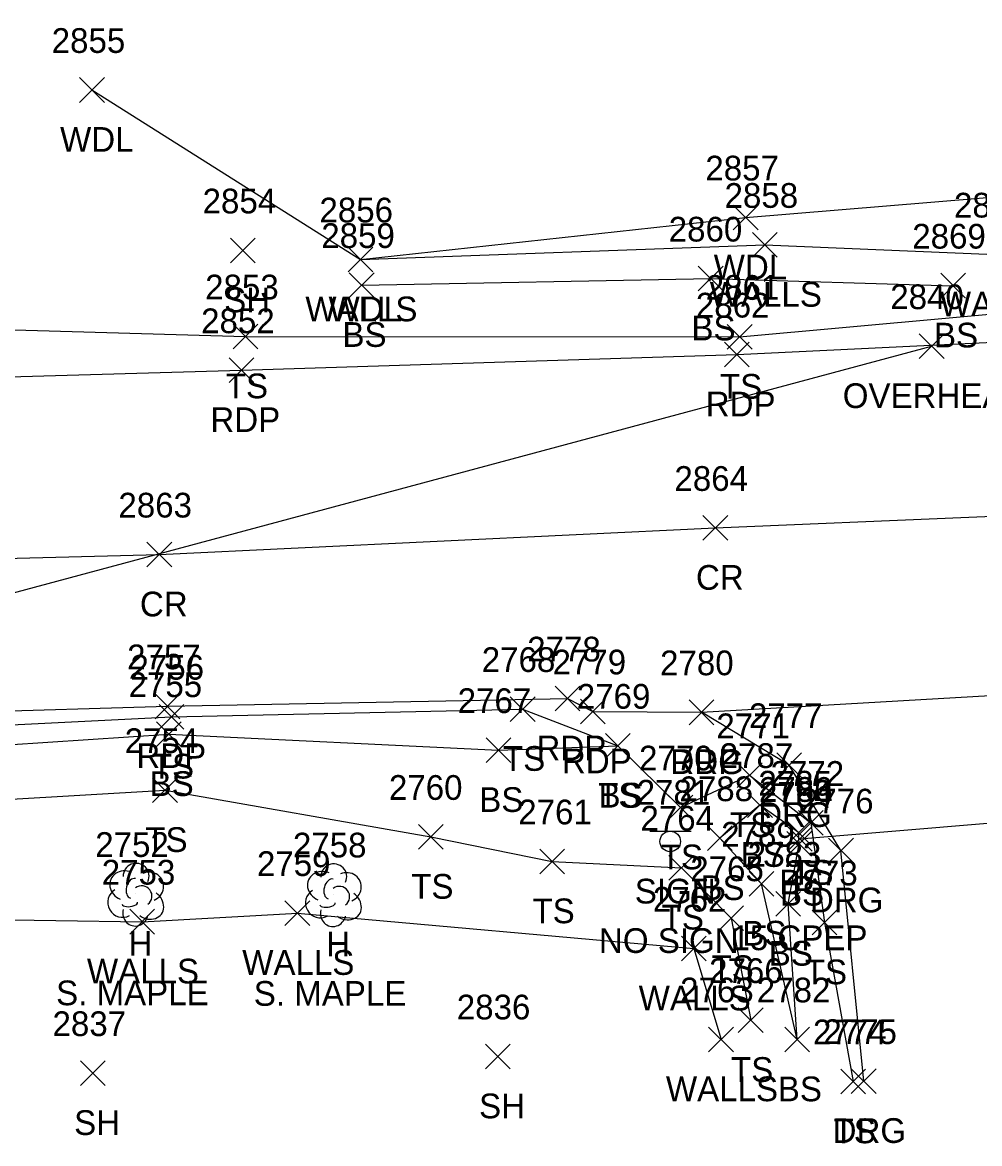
# Model space of a CAD drawing. Extents: x 1611797 to 1633212, y 298978 to 305475.
# Drawn here: x 1616071.8 to 1616149.2, y 301459.3 to 301550 of the extents above; entities that cross this region are included whole.
import ezdxf

# ---------------------------------------------------------------- set-up
doc = ezdxf.new("R2010")
doc.units = 0
for name, color, linetype in [('D_A', 7, 'Continuous'), ('D_C', 7, 'Continuous'), ('D_I', 7, 'Continuous'), ('D_TIC', 7, 'Continuous'), ('DCP', 7, 'Continuous'), ('L_A', 7, 'Continuous'), ('L_C', 7, 'Continuous'), ('L_I', 7, 'Continuous'), ('L_TIC', 7, 'Continuous'), ('LAWA', 7, 'Continuous'), ('LELB', 7, 'Continuous'), ('LTD', 7, 'Continuous'), ('LWS', 7, 'Continuous'), ('P_A', 7, 'Continuous'), ('P_I', 7, 'Continuous'), ('P_TIC', 7, 'Continuous'), ('PET', 7, 'Continuous'), ('PRC', 7, 'Continuous'), ('R_A', 7, 'Continuous'), ('R_I', 7, 'Continuous'), ('R_TIC', 7, 'Continuous'), ('RDG', 7, 'Continuous'), ('S_A', 7, 'Continuous'), ('S_C', 7, 'Continuous'), ('S_I', 7, 'Continuous'), ('SSGN', 7, 'Continuous'), ('U_A', 7, 'Continuous'), ('U_I', 7, 'Continuous'), ('U_TIC', 7, 'Continuous'), ('UCO', 7, 'Continuous')]:
    doc.layers.add(name, color=color, linetype=linetype)

msp = doc.modelspace()

# ---------------------------------------------------------------- linework, layer by layer
at = {"layer": 'D_TIC'}
for points in [[(1616133.638, 301482.967), (1616135.638, 301484.967)], [(1616135.638, 301482.967), (1616133.638, 301484.967)]]:
    msp.add_lwpolyline(points, dxfattribs=at)
at = {"layer": 'DCP'}
msp.add_lwpolyline([(1616134.638, 301483.967), (1616157.571, 301485.883)], dxfattribs=at)
at = {"layer": 'L_TIC'}
for points in [[(1616076.397, 301543.561), (1616078.397, 301545.561)], [(1616078.397, 301543.561), (1616076.397, 301545.561)], [(1616129.251, 301533.239), (1616131.251, 301535.239)], [(1616131.251, 301533.239), (1616129.251, 301535.239)], [(1616088.6, 301530.574), (1616090.6, 301532.574)], [(1616090.6, 301530.574), (1616088.6, 301532.574)], [(1616130.806, 301531.026), (1616132.806, 301533.026)], [(1616132.806, 301531.026), (1616130.806, 301533.026)], [(1616098.104, 301529.847), (1616100.104, 301531.847)], [(1616100.104, 301529.847), (1616098.104, 301531.847)], [(1616098.104, 301529.847), (1616100.104, 301531.847)], [(1616100.104, 301529.847), (1616098.104, 301531.847)], [(1616098.204, 301527.777), (1616100.204, 301529.777)], [(1616100.204, 301527.777), (1616098.204, 301529.777)], [(1616126.425, 301528.3), (1616128.425, 301530.3)], [(1616128.425, 301528.3), (1616126.425, 301530.3)], [(1616146.038, 301527.729), (1616148.038, 301529.729)], [(1616148.038, 301527.729), (1616146.038, 301529.729)], [(1616088.806, 301523.619), (1616090.806, 301525.619)], [(1616090.806, 301523.619), (1616088.806, 301525.619)], [(1616128.765, 301523.584), (1616130.765, 301525.584)], [(1616130.765, 301523.584), (1616128.765, 301525.584)], [(1616111.219, 301493.476), (1616113.219, 301495.476)], [(1616113.219, 301493.476), (1616111.219, 301495.476)], [(1616082.823, 301492.853), (1616084.823, 301494.853)], [(1616084.823, 301492.853), (1616082.823, 301494.853)], [(1616082.615, 301491.441), (1616084.615, 301493.441)], [(1616084.615, 301491.441), (1616082.615, 301493.441)], [(1616118.914, 301490.503), (1616120.914, 301492.503)], [(1616120.914, 301490.503), (1616118.914, 301492.503)], [(1616118.914, 301490.503), (1616120.914, 301492.503)], [(1616120.914, 301490.503), (1616118.914, 301492.503)], [(1616109.268, 301490.152), (1616111.268, 301492.152)], [(1616111.268, 301490.152), (1616109.268, 301492.152)], [(1616129.575, 301488.116), (1616131.575, 301490.116)], [(1616131.575, 301488.116), (1616129.575, 301490.116)], [(1616082.301, 301486.913), (1616084.301, 301488.913)], [(1616084.301, 301486.913), (1616082.301, 301488.913)], [(1616123.978, 301485.509), (1616125.978, 301487.509)], [(1616125.978, 301485.509), (1616123.978, 301487.509)], [(1616130.41, 301485.707), (1616132.41, 301487.707)], [(1616132.41, 301485.707), (1616130.41, 301487.707)], [(1616134.527, 301484.261), (1616136.527, 301486.261)], [(1616136.527, 301484.261), (1616134.527, 301486.261)], [(1616103.801, 301483.129), (1616105.801, 301485.129)], [(1616105.801, 301483.129), (1616103.801, 301485.129)], [(1616133.536, 301483.475), (1616135.536, 301485.475)], [(1616135.536, 301483.475), (1616133.536, 301485.475)], [(1616127.16, 301483.022), (1616129.16, 301485.022)], [(1616129.16, 301483.022), (1616127.16, 301485.022)], [(1616133.585, 301482.571), (1616135.585, 301484.571)], [(1616135.585, 301482.571), (1616133.585, 301484.571)], [(1616113.603, 301481.147), (1616115.603, 301483.147)], [(1616115.603, 301481.147), (1616113.603, 301483.147)], [(1616124.051, 301480.638), (1616126.051, 301482.638)], [(1616126.051, 301480.638), (1616124.051, 301482.638)], [(1616130.541, 301479.34), (1616132.541, 301481.34)], [(1616132.541, 301479.34), (1616130.541, 301481.34)], [(1616130.541, 301479.34), (1616132.541, 301481.34)], [(1616132.541, 301479.34), (1616130.541, 301481.34)], [(1616132.68, 301477.715), (1616134.68, 301479.715)], [(1616134.68, 301477.715), (1616132.68, 301479.715)], [(1616093.001, 301476.969), (1616095.001, 301478.969)], [(1616095.001, 301476.969), (1616093.001, 301478.969)], [(1616080.444, 301476.273), (1616082.444, 301478.273)], [(1616082.444, 301476.273), (1616080.444, 301478.273)], [(1616128.08, 301476.548), (1616130.08, 301478.548)], [(1616130.08, 301476.548), (1616128.08, 301478.548)], [(1616135.623, 301476.209), (1616137.623, 301478.209)], [(1616137.623, 301476.209), (1616135.623, 301478.209)], [(1616125.056, 301474.091), (1616127.056, 301476.091)], [(1616127.056, 301474.091), (1616125.056, 301476.091)], [(1616129.659, 301468.311), (1616131.659, 301470.311)], [(1616131.659, 301468.311), (1616129.659, 301470.311)], [(1616127.26, 301466.747), (1616129.26, 301468.747)], [(1616129.26, 301466.747), (1616127.26, 301468.747)], [(1616133.411, 301466.743), (1616135.411, 301468.743)], [(1616135.411, 301466.743), (1616133.411, 301468.743)], [(1616133.411, 301466.743), (1616135.411, 301468.743)], [(1616135.411, 301466.743), (1616133.411, 301468.743)], [(1616109.209, 301465.366), (1616111.209, 301467.366)], [(1616111.209, 301465.366), (1616109.209, 301467.366)], [(1616076.465, 301464.017), (1616078.465, 301466.017)], [(1616078.465, 301464.017), (1616076.465, 301466.017)], [(1616137.952, 301463.348), (1616139.952, 301465.348)], [(1616139.952, 301463.348), (1616137.952, 301465.348)]]:
    msp.add_lwpolyline(points, dxfattribs=at)
at = {"layer": 'LAWA'}
msp.add_lwpolyline([(1616077.397, 301544.561), (1616099.104, 301530.847), (1616130.251, 301534.239), (1616168.347, 301537.406), (1616206, 301540.224), (1616235.198, 301540.836), (1616280.164, 301546.271), (1616301.611, 301541.255), (1616300.857, 301550.027)], dxfattribs=at)
at = {"layer": 'LELB'}
for points in [[(1615704.044, 301519.429), (1615721.872, 301519.336), (1615766.347, 301519.497), (1615808.064, 301519.863), (1615851.206, 301519.772), (1615891.691, 301519.156), (1615938.875, 301519.331), (1615967.204, 301520.797), (1616008.295, 301523.113), (1616049.597, 301525.777), (1616089.806, 301524.619), (1616129.765, 301524.584), (1616155.631, 301526.935), (1616173.613, 301534.481), (1616188.642, 301527.741), (1616206.16, 301529.587), (1616236.465, 301530.233), (1616280.018, 301532.647)], [(1616099.204, 301528.777), (1616127.425, 301529.3), (1616147.038, 301528.729)], [(1615989.779, 301484.607), (1615994.61, 301488.827), (1616015.481, 301490.69), (1616050.954, 301492.21), (1616083.823, 301493.853), (1616112.219, 301494.476), (1616119.914, 301491.503), (1616124.978, 301486.509), (1616130.575, 301489.116), (1616135.527, 301485.261), (1616136.623, 301477.209), (1616138.952, 301464.348)], [(1615989.574, 301477.425), (1615992.854, 301483.301), (1616014.972, 301485.96), (1616050.97, 301490.273), (1616083.615, 301492.441), (1616110.268, 301491.152), (1616119.914, 301491.503)], [(1616042.737, 301484.507), (1616050.632, 301486.008), (1616083.301, 301487.913), (1616104.801, 301484.129), (1616114.603, 301482.147), (1616125.051, 301481.638), (1616129.08, 301477.548), (1616130.659, 301469.311)], [(1616134.411, 301467.743), (1616133.68, 301478.715), (1616134.585, 301483.571), (1616134.536, 301484.475), (1616131.41, 301486.707), (1616128.16, 301484.022), (1616131.541, 301480.34)], [(1616134.411, 301467.743), (1616131.541, 301480.34)]]:
    msp.add_lwpolyline(points, dxfattribs=at)
at = {"layer": 'LTD'}
for p, q in [((1616080.92, 301479.512), (1616080.92, 301479.512)), ((1616080.92, 301479.512), (1616080.92, 301479.512)), ((1616096.904, 301479.468), (1616096.904, 301479.468)), ((1616096.904, 301479.468), (1616096.904, 301479.468))]:
    msp.add_line(p, q, dxfattribs=at)
for centre in [(1616080.967, 301480.946), (1616096.951, 301480.902)]:
    msp.add_arc(centre, 1.047, 335.52715, 180.95627, dxfattribs=at)
for centre, major_axis, ratio, start_param, end_param in [((1616080.128, 301480.179), (1.21, -0.512), 0.895232, 1.570796, 4.712389), ((1616096.113, 301480.134), (1.21, -0.512), 0.895232, 1.570796, 4.712389), ((1616080.711, 301479.97), (-0.208, -0.792), 0.645439, 3.141593, 6.283185), ((1616081.961, 301480.096), (-1.141, -0.483), 0.949671, 1.570796, 4.712389), ((1616096.696, 301479.926), (-0.208, -0.792), 0.645439, 3.141593, 6.283185), ((1616097.946, 301480.051), (-1.141, -0.483), 0.949671, 1.570796, 4.712389), ((1616079.837, 301478.804), (0.584, -1.042), 0.959034, 3.141593, 6.283185), ((1616081.42, 301479.346), (-0.5, 0.667), 0.989748, 3.141593, 6.283185), ((1616095.821, 301478.759), (0.584, -1.042), 0.959034, 3.141593, 6.283185), ((1616097.404, 301479.301), (-0.5, 0.667), 0.989748, 3.141593, 6.283185), ((1616080.462, 301478.762), (-0.625, -0.083), 0.423636, 0, 3.141593), ((1616081.92, 301478.679), (-1.09, 0.792), 0.841452, 1.570796, 4.712389), ((1616096.446, 301478.718), (-0.625, -0.083), 0.423636, 0, 3.141593), ((1616097.905, 301478.634), (-1.09, 0.792), 0.841452, 1.570796, 4.712389), ((1616080.92, 301478.012), (0.265, 1.061), 0.942809, 1.570796, 4.712389), ((1616096.905, 301477.968), (0.265, 1.061), 0.942809, 1.570796, 4.712389)]:
    msp.add_ellipse(centre, major_axis=major_axis, ratio=ratio, start_param=start_param, end_param=end_param, dxfattribs=at)
at = {"layer": 'LWS'}
for points in [[(1616099.104, 301530.847), (1616131.806, 301532.026), (1616150.407, 301531.242)], [(1615991.045, 301479.401), (1616009.193, 301477.842), (1616046.524, 301477.786), (1616081.444, 301477.273), (1616094.001, 301477.969), (1616126.056, 301475.091), (1616128.26, 301467.747)]]:
    msp.add_lwpolyline(points, dxfattribs=at)
at = {"layer": 'P_TIC'}
for points in [[(1616128.535, 301522.151), (1616130.535, 301524.151)], [(1616130.535, 301522.151), (1616128.535, 301524.151)], [(1616088.483, 301520.885), (1616090.483, 301522.885)], [(1616090.483, 301520.885), (1616088.483, 301522.885)], [(1616126.799, 301508.126), (1616128.799, 301510.126)], [(1616128.799, 301508.126), (1616126.799, 301510.126)], [(1616081.84, 301505.971), (1616083.84, 301507.971)], [(1616083.84, 301505.971), (1616081.84, 301507.971)], [(1616114.848, 301494.324), (1616116.848, 301496.324)], [(1616116.848, 301494.324), (1616114.848, 301496.324)], [(1616082.497, 301493.695), (1616084.497, 301495.695)], [(1616084.497, 301493.695), (1616082.497, 301495.695)], [(1616116.905, 301493.278), (1616118.905, 301495.278)], [(1616118.905, 301493.278), (1616116.905, 301495.278)], [(1616125.676, 301493.21), (1616127.676, 301495.21)], [(1616127.676, 301493.21), (1616125.676, 301495.21)]]:
    msp.add_lwpolyline(points, dxfattribs=at)
at = {"layer": 'PET'}
for points in [[(1615966.818, 301518.281), (1616008.879, 301518.723), (1616050.011, 301520.759), (1616089.483, 301521.885), (1616129.535, 301523.151), (1616168.159, 301525.02), (1616195.535, 301526.207), (1616237.725, 301528.278), (1616279.261, 301529.047), (1616310.093, 301528.737), (1616346.909, 301526.936), (1616396.487, 301523.415), (1616418.702, 301521.734), (1616433.776, 301520.787), (1616436.26, 301522.002), (1616473.653, 301518.392)], [(1615957.121, 301489.367), (1615991.141, 301489.805), (1615993.646, 301491.148), (1616015.443, 301492.405), (1616050.86, 301493.726), (1616083.497, 301494.695), (1616115.848, 301495.324), (1616117.905, 301494.278), (1616126.676, 301494.21), (1616158.881, 301496.09), (1616172.109, 301497.829), (1616239.299, 301501.678), (1616275.912, 301502.338), (1616312.403, 301501.843), (1616375.815, 301498.508), (1616390.517, 301497.388), (1616390.666, 301497.624), (1616429.451, 301494.362), (1616470.741, 301491.131)]]:
    msp.add_lwpolyline(points, dxfattribs=at)
at = {"layer": 'PRC'}
msp.add_lwpolyline([(1615915.553, 301503.017), (1616010.706, 301505.129), (1616082.84, 301506.971), (1616127.799, 301509.126), (1616168.819, 301510.867), (1616237.813, 301513.845), (1616278.388, 301514.303), (1616314.288, 301513.683), (1616391.362, 301509.478), (1616432.286, 301506.326), (1616472.786, 301503.519), (1616513.149, 301500.749), (1616529.077, 301499.503), (1616571.59, 301496.851)], dxfattribs=at)
at = {"layer": 'R_TIC'}
for points in [[(1616125.676, 301493.21), (1616127.676, 301495.21)], [(1616127.676, 301493.21), (1616125.676, 301495.21)], [(1616132.776, 301488.936), (1616134.776, 301490.936)], [(1616134.776, 301488.936), (1616132.776, 301490.936)], [(1616136.959, 301482.027), (1616138.959, 301484.027)], [(1616138.959, 301482.027), (1616136.959, 301484.027)], [(1616138.794, 301463.373), (1616140.794, 301465.373)], [(1616140.794, 301463.373), (1616138.794, 301465.373)]]:
    msp.add_lwpolyline(points, dxfattribs=at)
at = {"layer": 'RDG'}
msp.add_lwpolyline([(1616139.794, 301464.373), (1616137.959, 301483.027), (1616133.776, 301489.936), (1616126.676, 301494.21)], dxfattribs=at)
at = {"layer": 'SSGN'}
for p, q in [((1616122.503, 301484.596), (1616125.836, 301484.596)), ((1616124.15, 301483.763), (1616124.15, 301483.763))]:
    msp.add_line(p, q, dxfattribs=at)
msp.add_circle((1616124.15, 301483.763), 0.833, dxfattribs=at)
at = {"layer": 'U_TIC'}
for points in [[(1616144.29, 301522.829), (1616146.29, 301524.829)], [(1616146.29, 301522.829), (1616144.29, 301524.829)]]:
    msp.add_lwpolyline(points, dxfattribs=at)
at = {"layer": 'UCO'}
msp.add_lwpolyline([(1616031.599, 301493.267), (1616145.29, 301523.829)], dxfattribs=at)

# ---------------------------------------------------------------- texts
at = {"layer": 'D_A'}
msp.add_text('P', height=2, dxfattribs=at).set_placement((1616134.016, 301478.967))
at = {"layer": 'D_C'}
msp.add_text('15 CPEP', height=2, dxfattribs=at).set_placement((1616129.103, 301474.967))
at = {"layer": 'D_I'}
msp.add_text('2786', height=2, dxfattribs=at).set_placement((1616131.323, 301486.967))
at = {"layer": 'L_A'}
for s, p in [('WDL', (1616074.815, 301539.561)), ('WDL', (1616127.668, 301529.239)), ('WALLS', (1616127.35, 301527.026)), ('SH', (1616088.088, 301526.574)), ('WALLS', (1616094.647, 301525.847)), ('WDL', (1616096.521, 301525.847)), ('WALLS', (1616145.95, 301526.242)), ('BS', (1616125.866, 301524.3)), ('BS', (1616097.645, 301523.777)), ('BS', (1616145.479, 301523.729)), ('TS', (1616088.215, 301519.619)), ('TS', (1616128.174, 301519.584)), ('TS', (1616110.629, 301489.476)), ('TS', (1616082.233, 301488.853)), ('BS', (1616082.056, 301487.441)), ('BS', (1616108.709, 301486.152)), ('TS', (1616118.324, 301486.503)), ('BS', (1616118.355, 301486.503)), ('TS', (1616128.984, 301484.116)), ('TS', (1616081.71, 301482.913)), ('TS', (1616123.387, 301481.509)), ('BS', (1616129.851, 301481.707)), ('BS', (1616132.977, 301479.475)), ('TS', (1616133.937, 301480.261)), ('TS', (1616103.21, 301479.129)), ('BS', (1616126.601, 301479.022)), ('BS', (1616133.026, 301478.571)), ('TS', (1616113.013, 301477.147)), ('TS', (1616123.461, 301476.638)), ('BS', (1616129.982, 301475.34)), ('BS', (1616129.982, 301475.34)), ('H', (1616080.353, 301474.512)), ('H', (1616096.337, 301474.468)), ('BS', (1616132.121, 301473.715)), ('WALLS', (1616076.987, 301472.273)), ('WALLS', (1616089.545, 301472.969)), ('TS', (1616127.49, 301472.548)), ('TS', (1616135.033, 301472.209)), ('WALLS', (1616121.6, 301470.091)), ('TS', (1616129.068, 301464.311)), ('WALLS', (1616123.804, 301462.747)), ('BS', (1616132.852, 301462.743)), ('BS', (1616132.852, 301462.743)), ('SH', (1616108.697, 301461.366)), ('SH', (1616075.953, 301460.017)), ('TS', (1616137.362, 301459.348))]:
    msp.add_text(s, height=2, dxfattribs=at).set_placement(p)
at = {"layer": 'L_C'}
for p in [(1616074.495, 301470.512), (1616090.479, 301470.468)]:
    msp.add_text('S. MAPLE', height=2, dxfattribs=at).set_placement(p)
at = {"layer": 'L_I'}
for s, p in [('2855', (1616074.138, 301547.561)), ('2857', (1616126.991, 301537.239)), ('2858', (1616128.546, 301535.026)), ('2854', (1616086.34, 301534.574)), ('2868', (1616147.1, 301534.242)), ('2856', (1616095.789, 301533.847)), ('2856', (1616095.789, 301533.847)), ('2860', (1616124.031, 301532.3)), ('2859', (1616095.937, 301531.777)), ('2869', (1616143.723, 301531.729)), ('2853', (1616086.546, 301527.619)), ('2861', (1616127.025, 301527.584)), ('2756', (1616080.508, 301496.853)), ('2768', (1616108.912, 301497.476)), ('2755', (1616080.355, 301495.441)), ('2767', (1616106.961, 301494.152)), ('2769', (1616116.6, 301494.503)), ('2769', (1616116.6, 301494.503)), ('2771', (1616127.882, 301492.116)), ('2754', (1616080.041, 301490.913)), ('2770', (1616121.631, 301489.509)), ('2787', (1616128.15, 301489.707)), ('2772', (1616132.268, 301488.261)), ('2760', (1616101.407, 301487.129)), ('2788', (1616124.901, 301487.022)), ('2785', (1616131.276, 301487.475)), ('2784', (1616131.326, 301486.571)), ('2761', (1616111.863, 301485.147)), ('2764', (1616121.744, 301484.638)), ('2789', (1616128.273, 301483.34)), ('2789', (1616128.273, 301483.34)), ('2752', (1616077.66, 301482.512)), ('2758', (1616093.645, 301482.468)), ('2783', (1616130.421, 301481.715)), ('2759', (1616090.734, 301480.969)), ('2765', (1616125.773, 301480.548)), ('2753', (1616078.184, 301480.273)), ('2773', (1616133.364, 301480.209)), ('2762', (1616122.749, 301478.091)), ('2766', (1616127.297, 301472.311)), ('2763', (1616124.953, 301470.747)), ('2782', (1616131.152, 301470.743)), ('2782', (1616131.152, 301470.743)), ('2836', (1616106.894, 301469.366)), ('2837', (1616074.206, 301468.017)), ('2774', (1616135.692, 301467.348))]:
    msp.add_text(s, height=2, dxfattribs=at).set_placement(p)
at = {"layer": 'P_A'}
for s, p in [('RDP', (1616127.023, 301518.151)), ('RDP', (1616086.971, 301516.885)), ('CR', (1616126.232, 301504.126)), ('CR', (1616081.273, 301501.971)), ('RDP', (1616080.986, 301489.695)), ('RDP', (1616113.336, 301490.324)), ('RDP', (1616115.393, 301489.278)), ('RDP', (1616124.164, 301489.21))]:
    msp.add_text(s, height=2, dxfattribs=at).set_placement(p)
at = {"layer": 'P_I'}
for s, p in [('2862', (1616126.228, 301526.151)), ('2852', (1616086.223, 301524.885)), ('2864', (1616124.492, 301512.126)), ('2863', (1616079.533, 301509.971)), ('2757', (1616080.238, 301497.695)), ('2778', (1616112.588, 301498.324)), ('2779', (1616114.638, 301497.278)), ('2780', (1616123.33, 301497.21))]:
    msp.add_text(s, height=2, dxfattribs=at).set_placement(p)
at = {"layer": 'R_A'}
for p in [(1616124.164, 301489.21), (1616131.264, 301484.936), (1616135.447, 301478.027), (1616137.282, 301459.373)]:
    msp.add_text('DRG', height=2, dxfattribs=at).set_placement(p)
at = {"layer": 'R_I'}
for s, p in [('2780', (1616123.33, 301497.21)), ('2777', (1616130.516, 301492.936)), ('2776', (1616134.644, 301486.027)), ('2775', (1616136.534, 301467.373))]:
    msp.add_text(s, height=2, dxfattribs=at).set_placement(p)
at = {"layer": 'S_A'}
msp.add_text('SIGN', height=2, dxfattribs=at).set_placement((1616121.288, 301478.743))
at = {"layer": 'S_C'}
msp.add_text('NO SIGN', height=2, dxfattribs=at).set_placement((1616118.39, 301474.743))
at = {"layer": 'S_I'}
msp.add_text('2781', height=2, dxfattribs=at).set_placement((1616121.438, 301486.743))
at = {"layer": 'U_A'}
msp.add_text('OVERHEAD', height=2, dxfattribs=at).set_placement((1616138.102, 301518.829))
at = {"layer": 'U_I'}
msp.add_text('2840', height=2, dxfattribs=at).set_placement((1616141.944, 301526.829))

doc.saveas('drawing.dxf')
